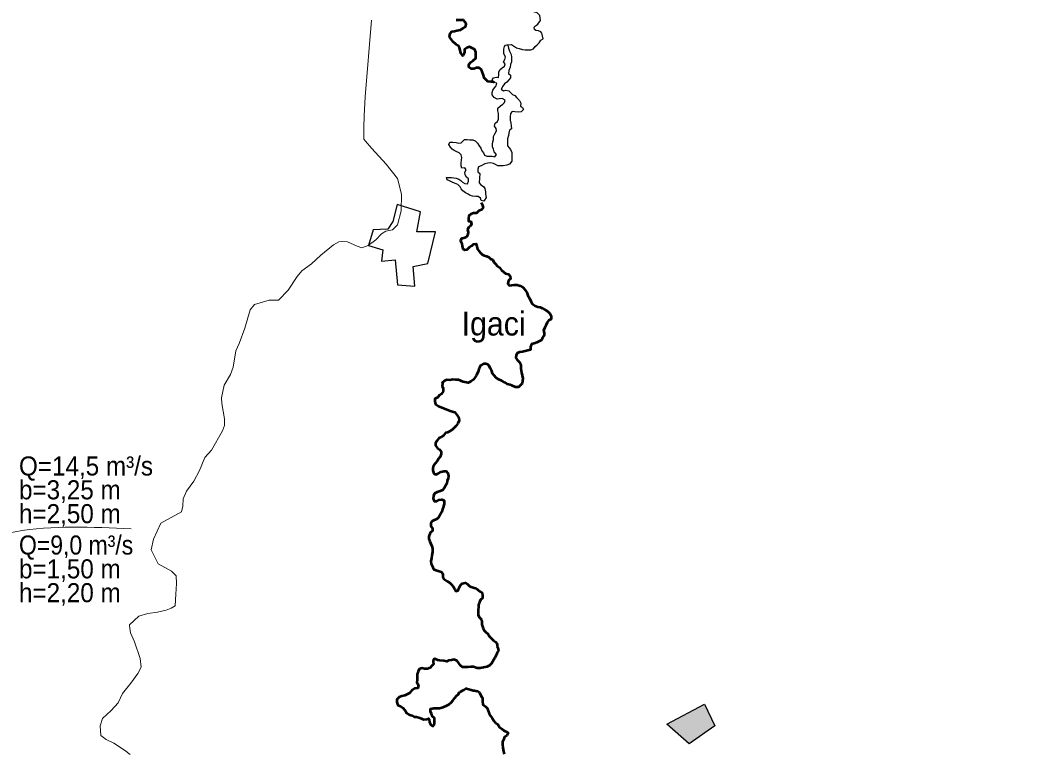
# Model space of a CAD drawing. Extents: x -1643653 to 4543381, y 1624270 to 13878484.
# Drawn here: x 752066 to 773010, y 8933563 to 8948961 of the extents above; entities that cross this region are included whole.
import ezdxf

# ---------------------------------------------------------------- set-up
doc = ezdxf.new("R2010")
doc.units = 0
doc.header["$LTSCALE"] = 160
doc.linetypes.add('MEDIUM_DASHED', pattern=[4.5, 3, -1.5])
for name, color, linetype, lineweight in [('10', 7, 'MEDIUM_DASHED', 60), ('14', 7, 'Continuous', 13), ('21', 7, 'Continuous', 25), ('24', 7, 'Continuous', 25), ('50', 7, 'Continuous', 13), ('60', 7, 'Continuous', 13)]:
    doc.layers.add(name, color=color, linetype=linetype, lineweight=lineweight)
doc.layers.add('41', color=7, linetype='Continuous')

msp = doc.modelspace()

# ---------------------------------------------------------------- hatches: boundary and pattern name
at = {"layer": '21'}
msp.add_hatch(color=256, dxfattribs=at).paths.add_polyline_path([(765624.2, 8934185.8), (766418.4, 8934607.9), (766636, 8934155.3), (766095.9, 8933780)])

# ---------------------------------------------------------------- linework, layer by layer
at = {"layer": '10'}
msp.add_open_spline([(753774.9, 8926261.4), (753812.7, 8926399.9), (753812, 8926558.8), (753709.5, 8926687.3), (753566, 8926867.3), (753376.7, 8926916.9), (753227, 8927050.3), (753014.8, 8927239.4), (752804.9, 8927430.3), (752597.6, 8927630.5), (752376.7, 8927843.7), (752192.2, 8928091.3), (752017.6, 8928334.1), (751956, 8928419.6), (752103.6, 8928574.9), (752029.9, 8928655), (751955.6, 8928735.8), (751801.6, 8928688.1), (751721.4, 8928753.8), (751652.2, 8928810.4), (751601.3, 8928901.2), (751523.9, 8928951.3), (751367.8, 8929052.4), (751185.2, 8929119.1), (751030.2, 8929222.8), (750931.1, 8929289.2), (750854.8, 8929393), (750746.4, 8929445), (750665, 8929484.1), (750582.4, 8929520.3), (750499.6, 8929556.1), (750413.3, 8929593.4), (750326.8, 8929630.1), (750240.4, 8929667.2), (750059.5, 8929745.1), (749875.6, 8929807.6), (749709.7, 8929926.4), (749552.8, 8930038.9), (749714.4, 8930314.8), (749771.5, 8930481.9), (749848.6, 8930707.8), (750077.8, 8930926.7), (750119.5, 8931152.3), (750152, 8931328.4), (750058.1, 8931532.9), (749922, 8931707.8), (749753.2, 8931924.7), (749391.3, 8931773.6), (749243.2, 8931979.4), (749032.7, 8932271.9), (748906.3, 8932592.6), (748823.6, 8932929.9), (748786.3, 8933082.2), (748758.3, 8933247.9), (748811.3, 8933399), (748934, 8933748.4), (749210.7, 8934002.5), (749514.7, 8934226), (749629.1, 8934310.1), (749795.5, 8934228.1), (749909.7, 8934329.8), (749982.5, 8934394.6), (750061.5, 8934468.6), (750045.4, 8934552), (750025.6, 8934654.5), (749991.4, 8934758.2), (749959, 8934860.6), (749901, 8935043.9), (749870.4, 8935232.4), (749773.9, 8935403.7), (749725.3, 8935490), (749619.5, 8935521), (749551.8, 8935588.9), (749459.7, 8935681.1), (749373.5, 8935781.5), (749280.2, 8935872.8), (749090.8, 8936058.2), (748862, 8936191), (748663.2, 8936378.9), (748545.5, 8936490.1), (748390.4, 8936617), (748404, 8936773.9), (748412.2, 8936868.5), (748420.5, 8936963.2), (748428.7, 8937057.8)], degree=3, dxfattribs=at)
at = {"layer": '14'}
for points in [[(756356.5, 8940591.2), (756296.6, 8940917.4), (756291.9, 8941034.6), (756343.8, 8941299.3), (756482.2, 8941523.2), (756533.7, 8941676), (756591, 8942022.3), (756657.8, 8942175), (756781.3, 8942495.7), (756894.8, 8942882.6), (756981.8, 8942989.4), (757287.8, 8943085.7), (757486.4, 8943080.2), (757685.9, 8943293.8), (757875.4, 8943578.7), (757972.7, 8943700.8), (758177, 8943848.1), (758371.2, 8944026.1), (758642, 8944244.6), (758749.2, 8944310.6), (758825.7, 8944315.6), (758932.7, 8944310.3), (759136.1, 8944213.1), (759232.8, 8944182.4), (759365.4, 8944228), (759528.8, 8944349.9), (759646.5, 8944477.1), (759733.3, 8944533), (759876, 8944558.2), (759978.3, 8944665), (760060.9, 8944960.3), (760062.2, 8945306.7), (759981.9, 8945637.9), (759743.6, 8945938.9), (759444.2, 8946265.5), (759307.2, 8946418.6), (759276.8, 8946459.4), (759277.1, 8946556.2), (759272.6, 8946703.9), (759283.7, 8946948.4), (759300.4, 8947350.8), (759434.4, 8948959.2)], [(753980.4, 8934477.6), (754123.7, 8934635.3), (754216.1, 8934833.8), (754390.1, 8935047.4), (754533.5, 8935250.9), (754605.3, 8935388.3), (754585.6, 8935566.6), (754469.7, 8935913.2), (754383.8, 8936101.9), (754363.9, 8936249.7), (754364, 8936275.1), (754558.3, 8936453.1), (754747, 8936508.7), (754950.8, 8936538.9), (755129.3, 8936579.4), (755236.5, 8936625), (755318.1, 8936670.7), (755334.3, 8936915.2), (755350.4, 8937139.3), (755340.8, 8937302.3), (755239.3, 8937399.3), (754959.7, 8937552.6), (754813, 8937843.3), (754864.8, 8938067.3), (755018.9, 8938408.3), (755238.3, 8938525.1), (755452.7, 8938641.9), (755478.6, 8938759), (755489.4, 8938916.9), (755556.2, 8939074.7), (755709.8, 8939283.3), (755832.9, 8939512.3), (755940.9, 8939782.1), (756079, 8939934.6), (756314.8, 8940341.7), (756356, 8940453.7), (756356.5, 8940591.2)], [(754379.5, 8933549.8), (754257.6, 8933646.8), (754033.9, 8933789.8), (753871.2, 8933866.5), (753759.4, 8933948.2), (753744.9, 8934152), (753796.4, 8934304.8), (753980.4, 8934477.6)]]:
    msp.add_lwpolyline(points, dxfattribs=at)
at = {"layer": '21'}
for points in [[(759971.8, 8945092.7), (759884.4, 8944737), (759777.9, 8944573.9), (759473.6, 8944557.9), (759374.4, 8944228.2), (759675.4, 8944141.8), (759642.3, 8943899.6), (759934.4, 8943928.7), (759980.7, 8943402.3), (760347, 8943377.8), (760309.6, 8943788.8), (760615.6, 8943855.9), (760776.1, 8944516.6), (760383.6, 8944516.3), (760460.4, 8944936.4)], [(765624.2, 8934185.8), (766418.4, 8934607.9), (766636, 8934155.3), (766095.9, 8933780)]]:
    msp.add_lwpolyline(points, close=True, dxfattribs=at)
at = {"layer": '24', "lineweight": 53}
for p, q in [((761210.9, 8948956.2), (761361.4, 8948961.1)), ((761361.4, 8948961.1), (761210.9, 8948956.2))]:
    msp.add_line(p, q, dxfattribs=at)
at = {"layer": '24'}
for points in [[(762975.5, 8948950.6), (762963.4, 8949056), (762906, 8949108.6), (762836.6, 8949131.3), (762820.1, 8949147.2), (762725, 8949191.5), (762705.8, 8949206.6), (762661.7, 8949253.3), (762654.7, 8949294.5)], [(763037.7, 8948563.4), (763016, 8948657.7), (763008.9, 8948685.8), (762983.9, 8948709.2), (762933.4, 8948733.1), (762882.7, 8948741.6), (762855.1, 8948762.5), (762848.4, 8948813.6), (762871.8, 8948838.7), (762897.5, 8948853.6), (762923.3, 8948873.5), (762959.9, 8948923.9), (762975.6, 8948949.1), (762975.5, 8948950.6)], [(762274.4, 8948440.9), (762371.2, 8948443.4), (762477.5, 8948379.6), (762533.3, 8948364), (762599.3, 8948343.2), (762655.2, 8948337.7), (762711.2, 8948337.4), (762777.3, 8948337), (762828.3, 8948357), (762869.3, 8948402.6), (762910.2, 8948443.1), (762951.2, 8948483.6), (762987.1, 8948534.3), (763037.7, 8948563.4)], [(762294.6, 8948431.6), (762309.4, 8948370.4), (762329.3, 8948309.2), (762354.4, 8948253), (762369.3, 8948196.8), (762368.9, 8948145.9), (762368.5, 8948079.7), (762352.8, 8948023.8), (762342.2, 8947967.8), (762311.3, 8947901.8), (762310.9, 8947840.7), (762351.3, 8947804.7), (762350.9, 8947748.7), (762315, 8947703.1), (762274, 8947657.5), (762222.9, 8947622.2), (762186.9, 8947571.5), (762156, 8947510.5), (762201.5, 8947474.6), (762252.5, 8947489.6), (762313.4, 8947473.9), (762353.8, 8947432.9), (762394.3, 8947396.9), (762439.9, 8947376.3), (762480.3, 8947330.2), (762535.8, 8947273.8), (762565.9, 8947212.5), (762560.5, 8947156.5), (762600.9, 8947125.7), (762621, 8947079.7), (762569.8, 8947034.2), (762508.7, 8947029.5), (762437.6, 8947035), (762381.7, 8947040.5), (762350.9, 8946999.9), (762340.2, 8946928.7), (762339.7, 8946862.4), (762354.5, 8946796.1), (762364.3, 8946740), (762369, 8946678.9), (762328.1, 8946648.6), (762312.4, 8946587.6), (762307, 8946536.7), (762286.2, 8946470.6), (762285.7, 8946394.2), (762285.2, 8946322.8), (762320.5, 8946281.9), (762350.7, 8946240.9), (762375.7, 8946179.6), (762375.3, 8946123.6), (762380, 8946057.4), (762374.5, 8946001.4), (762328.3, 8945935.4), (762272.2, 8945915.4), (762195.8, 8945900.6), (762134.8, 8945901), (762083.9, 8945901.3), (762038.3, 8945927.1), (761992.7, 8945947.8), (761931.8, 8945963.4), (761875.8, 8945958.7), (761809.6, 8945943.9), (761738.1, 8945903.6), (761682, 8945883.6), (761666.4, 8945832.7), (761666, 8945776.7), (761706.4, 8945740.8), (761694.9, 8945542.2), (761725.1, 8945501.2), (761781.5, 8945468.3), (761814.4, 8945424.2), (761825.4, 8945358.2), (761825.4, 8945314.1), (761836.4, 8945237.1), (761803.4, 8945182), (761788.9, 8945159.5), (761738.1, 8945175.1), (761723.2, 8945226.2), (761672.6, 8945257.1), (761621.7, 8945257.4), (761555.6, 8945262.9), (761504.9, 8945278.5), (761459.3, 8945304.3), (761403.6, 8945335.2), (761347.9, 8945376.3), (761312.6, 8945417.3), (761292.5, 8945463.3), (761247.1, 8945509.4), (761176.1, 8945540.4), (761125.4, 8945561.1), (761069.6, 8945586.9), (761024, 8945607.6), (761009.1, 8945658.6), (761059.9, 8945658.3), (761110.8, 8945658), (761161.6, 8945647.5), (761212.4, 8945642.1), (761263.1, 8945621.4), (761308.7, 8945595.6), (761344.1, 8945559.7), (761389.6, 8945528.9)], [(761389.6, 8945528.9), (761450.6, 8945523.4), (761471.3, 8945579.3), (761466.6, 8945630.2), (761426.1, 8945661.1), (761401.1, 8945712.2), (761391.3, 8945768.3), (761422.1, 8945819), (761391.9, 8945859.9), (761330.8, 8945850.2), (761315.9, 8945901.2), (761316.3, 8945967.4), (761321.8, 8946018.3), (761332.3, 8946074.3), (761317.5, 8946135.5), (761272, 8946171.4), (761221.3, 8946192.1), (761165.5, 8946223.1), (761125, 8946253.9), (761089.7, 8946294.9), (761059.6, 8946351.1), (761080.2, 8946396.8), (761141.3, 8946396.4), (761207.4, 8946390.9), (761263.2, 8946380.3), (761314.1, 8946385.1), (761350, 8946420.5), (761385.8, 8946456), (761441.8, 8946455.6), (761497.7, 8946450.2), (761558.7, 8946449.8), (761609.4, 8946429.1), (761659.9, 8946377.8), (761690.1, 8946321.6), (761725.3, 8946270.4), (761750.4, 8946214.2), (761785.7, 8946173.2), (761805.7, 8946122.2), (761856.4, 8946106.6), (761917.4, 8946101.1), (761968.3, 8946100.8), (762019.1, 8946090.2), (762055, 8946135.8), (762009.7, 8946197.3), (761994.7, 8946248.3), (761974.8, 8946299.4), (761970.1, 8946355.4), (761980.6, 8946406.3), (761996.2, 8946457.1), (761991.5, 8946518.3), (762022.4, 8946574.1), (762053.3, 8946635.1), (762048.6, 8946686), (762013.3, 8946732.1), (762029, 8946793.1), (762075.1, 8946833.6), (762095.7, 8946879.3), (762096.2, 8946945.5), (762096.5, 8946996.4), (762086.8, 8947057.6), (762082.1, 8947113.7), (762138.3, 8947159.2), (762189.4, 8947194.5), (762225.3, 8947229.9), (762235.8, 8947280.8), (762175, 8947311.8), (762119, 8947307), (762068.1, 8947302.3), (762007.3, 8947338.3), (761967, 8947389.5), (761967.3, 8947440.4), (761977.9, 8947491.3), (762013.8, 8947536.9), (762049.7, 8947577.4), (762060.2, 8947633.4), (761999.3, 8947649.1), (761964.1, 8947705.3), (761994.9, 8947745.9), (762045.8, 8947760.8), (762096.7, 8947755.4), (762107.2, 8947816.5), (762107.6, 8947872.5), (762133.4, 8947923.3), (762174.3, 8947958.7), (762220.3, 8947989), (762235.9, 8948039.8), (762205.7, 8948080.7), (762231.5, 8948131.5), (762247.1, 8948187.4), (762212, 8948248.8), (762212.3, 8948299.7), (762212.7, 8948350.7), (762226.4, 8948402.4), (762246.6, 8948432.3), (762274.4, 8948440.9), (762294.6, 8948431.6)]]:
    msp.add_lwpolyline(points, dxfattribs=at)
at = {"layer": '24', "lineweight": 53}
for points in [[(762015.2, 8947645), (761987.8, 8947662.2), (761936.9, 8947662.5), (761870.9, 8947668), (761835.5, 8947709), (761800.2, 8947750), (761780.2, 8947801), (761760.3, 8947857.2), (761740.3, 8947913.3), (761694.9, 8947959.5), (761638.9, 8947954.7), (761577.7, 8947934.7), (761526.9, 8947935), (761476.3, 8947971), (761476.6, 8948027), (761517.6, 8948072.6), (761568.7, 8948107.9), (761625, 8948158.5), (761625.5, 8948219.6), (761620.8, 8948285.9), (761600.9, 8948342), (761489.4, 8948398.8), (761433.3, 8948378.7), (761387.2, 8948338.3), (761386.8, 8948277.2), (761350.7, 8948206.1), (761310.4, 8948262.3), (761295.6, 8948328.7), (761280.7, 8948379.7), (761255.6, 8948425.7), (761204.9, 8948451.5), (761149.3, 8948502.7), (761098.9, 8948564.2), (761068.7, 8948610.2), (761084.4, 8948676.3), (761120.3, 8948716.8), (761176.3, 8948726.7), (761227.3, 8948741.7), (761298.6, 8948756.5), (761359.8, 8948791.8), (761405.8, 8948816.9), (761421.4, 8948872.9), (761391.3, 8948924), (761361.4, 8948961.1)], [(761737.3, 8945134.7), (761755.2, 8945087.5), (761775.2, 8945026.3), (761739.2, 8944980.7), (761683.1, 8944955.6), (761637, 8944910), (761576, 8944905.3), (761514.8, 8944890.4), (761479, 8944855), (761468.4, 8944799), (761468, 8944743), (761518.8, 8944732.5), (761533.7, 8944681.5), (761513.1, 8944635.7), (761467.1, 8944610.6), (761451.5, 8944559.7), (761461.3, 8944508.7), (761455.9, 8944457.8), (761425, 8944407.1), (761374, 8944381.9), (761323.1, 8944377.2), (761302.4, 8944331.5), (761327.5, 8944275.3), (761337.3, 8944219.2), (761347.1, 8944163.1), (761392.7, 8944142.4), (761443.6, 8944147.2), (761489.7, 8944192.7), (761535.7, 8944223), (761576.6, 8944258.4), (761632.6, 8944263.1), (761642.4, 8944212.1), (761657.3, 8944156), (761687.5, 8944115.1), (761717.7, 8944074.1), (761753.1, 8944038.2), (761798.7, 8944017.6), (761849.5, 8944007), (761895.2, 8943986.4), (761930.5, 8943950.5), (761981.2, 8943929.8), (762001.3, 8943883.8), (762036.6, 8943842.8), (762071.9, 8943801.9), (762117.5, 8943771), (762157.7, 8943709.6), (762203.3, 8943678.8), (762243.7, 8943642.8), (762304.7, 8943627.2), (762340, 8943586.2), (762349.8, 8943530.1), (762308.8, 8943494.7), (762293.1, 8943428.6), (762323.4, 8943387.7), (762374.3, 8943397.5), (762425.2, 8943407.4), (762486.2, 8943407), (762552.2, 8943386.2), (762613, 8943350.1), (762653.4, 8943309.1), (762693.7, 8943242.6), (762713.6, 8943181.4), (762748.8, 8943125.1), (762773.8, 8943063.8), (762803.9, 8943007.6)], [(762803.9, 8943007.6), (762864.7, 8942966.5), (762920.5, 8942940.7), (762971.3, 8942935.2), (763016.9, 8942914.6), (763077.7, 8942878.5), (763133.4, 8942842.5), (763173.8, 8942801.5), (763203.9, 8942745.3), (763203.5, 8942684.1), (763147.4, 8942659), (763116.6, 8942613.4), (763095.9, 8942567.7), (763070.1, 8942511.8), (763044.2, 8942445.8), (763054, 8942394.8), (763058.8, 8942343.8), (763022.9, 8942303.3), (763002.2, 8942247.4), (762946, 8942217.2), (762900.1, 8942197.1), (762849.1, 8942177), (762787.9, 8942157.1), (762767.2, 8942101.2), (762766.8, 8942045.1), (762710.7, 8942025.1), (762659.8, 8942010.2), (762598.7, 8942000.3), (762537.6, 8941995.7), (762486.6, 8941970.5), (762465.9, 8941924.8), (762460.5, 8941873.9), (762490.7, 8941832.9), (762526.1, 8941797.1), (762561.4, 8941756.1), (762566.1, 8941705.1), (762565.7, 8941649.1)], [(762565.7, 8941649.1), (762580.6, 8941564.2), (762580.6, 8941564.2), (762611.1, 8941442.4), (762595.8, 8941335.7), (762519.6, 8941259.6), (762453.6, 8941259.6), (762377.4, 8941292.5), (762340.6, 8941308.9), (762279.2, 8941321.2), (762230.1, 8941353.9), (762164.6, 8941394.8), (762103.2, 8941419.3), (762051.3, 8941456.8), (762010.3, 8941499.8), (761975, 8941545.9), (761955, 8941597), (761924.9, 8941658.3), (761899.8, 8941709.4), (761871.3, 8941731.8), (761831, 8941748.4), (761783.1, 8941745.8), (761721.9, 8941715.6), (761696, 8941655.9), (761672.3, 8941589.5), (761634.4, 8941513.7), (761596.5, 8941447.3), (761568.1, 8941409.3), (761520.8, 8941376.1), (761463.9, 8941352.4), (761392.8, 8941366.6), (761355, 8941371.4), (761307.6, 8941390.3), (761257, 8941413), (761201, 8941413.3), (761140, 8941418.8), (761080.2, 8941404.6), (761018.6, 8941409.3), (760966.5, 8941390.3), (760919.1, 8941352.4), (760920.8, 8941343.8), (760920.4, 8941282.7), (760935.3, 8941231.7), (760934.8, 8941165.4), (760904, 8941119.8), (760852.9, 8941089.6), (760830.3, 8941047.1), (760764.8, 8941010.3), (760764.8, 8941010.3), (760764.8, 8940957.1), (760780.4, 8940901.6), (760841.2, 8940860.4), (761104.9, 8940756.8), (761184.4, 8940731.1), (761241.3, 8940660), (761269.7, 8940617.3), (761272.5, 8940557.8), (761245.1, 8940495.9), (761203.9, 8940441), (761135.3, 8940372.3), (761059.8, 8940324.2), (761025.5, 8940310.4), (760989.9, 8940299.1), (760943.7, 8940243.4), (760902.8, 8940208)], [(760902.8, 8940208), (760846.7, 8940188), (760810.8, 8940142.4), (760779.9, 8940086.5), (760779.6, 8940035.6), (760819.8, 8939979.3), (760860.3, 8939948.5), (760895.7, 8939907.5), (760895.3, 8939856.6), (760874.5, 8939795.6), (760833.5, 8939750), (760812.9, 8939704.3), (760777, 8939663.8), (760736, 8939613.1), (760720.3, 8939562.2), (760720, 8939511.3), (760739.9, 8939450.1), (760785.6, 8939429.4), (760831.5, 8939449.5), (760892.7, 8939484.7), (760948.8, 8939499.7), (760999.7, 8939499.3), (761034.9, 8939453.3), (761049.8, 8939397.1), (761044.3, 8939341.1), (761023.6, 8939290.3), (761013.1, 8939239.5), (760977.1, 8939183.7), (760956.5, 8939137.9), (760920.6, 8939097.4), (760874.7, 8939077.3), (760813.5, 8939057.4), (760757.3, 8939027.2), (760736.7, 8938976.4), (760726.1, 8938920.4), (760746.1, 8938869.3), (760802, 8938869)], [(760802, 8938869), (760853.1, 8938894.1), (760909.1, 8938903.9), (760959.8, 8938878.1), (760959.4, 8938817), (760943.7, 8938756), (760923, 8938700.1), (760907.3, 8938644.2), (760881.5, 8938593.4), (760845.5, 8938532.5), (760809.7, 8938497.1), (760707.6, 8938446.8), (760676.7, 8938396), (760676.3, 8938340), (760711.7, 8938304.1), (760711.3, 8938243), (760665.2, 8938202.6), (760639.3, 8938126.3), (760638.9, 8938075.4), (760658.9, 8938024.3), (760678.9, 8937973.2), (760698.9, 8937922.2), (760713.8, 8937871.1), (760713.3, 8937804.9), (760697.6, 8937728.6), (760692.1, 8937672.6), (760676.4, 8937606.5), (760686.2, 8937555.5), (760706.2, 8937509.5), (760736.3, 8937443.1), (760781.9, 8937417.3), (760832.7, 8937406.8), (760898.7, 8937386), (760928.9, 8937345.1), (760933.5, 8937278.8), (760958.6, 8937232.8), (761024.5, 8937191.7), (761075.1, 8937155.7), (761110.4, 8937119.8), (761145.7, 8937073.7), (761181, 8937022.6), (761201, 8936976.6), (761252, 8936996.6), (761272.7, 8937047.4), (761298.5, 8937103.3), (761334.4, 8937138.7), (761400.6, 8937153.6), (761451.3, 8937127.8), (761491.7, 8937086.8), (761547.5, 8937066.1), (761608.4, 8937045.3), (761659, 8937014.4), (761704.5, 8936973.4), (761755.2, 8936947.6), (761765, 8936891.5), (761764.6, 8936835.4), (761723.7, 8936800), (761703, 8936749.2), (761682.2, 8936693.3), (761676.8, 8936642.4), (761671.3, 8936586.4), (761671, 8936535.5), (761670.6, 8936479.5), (761695.7, 8936433.5), (761741.2, 8936387.3)], [(761741.2, 8936387.3), (761751, 8936336.3), (761750.6, 8936280.3), (761775.5, 8936198.6), (761795.5, 8936152.7), (761830.9, 8936116.8), (761876.4, 8936080.8), (761911.7, 8936029.7), (761952.1, 8935988.7), (761992.4, 8935942.6), (762038, 8935916.8), (762073.3, 8935875.8), (762073, 8935819.8), (762081.2, 8935792.2), (762095.5, 8935735.1), (762067, 8935692.3), (762052.7, 8935649.5), (762024.2, 8935578.2), (761953, 8935464), (761910.2, 8935421.2), (761853.2, 8935392.7), (761710.7, 8935364.1), (761653.7, 8935364.1), (761576.7, 8935395.1), (761520.7, 8935390.3), (761459.6, 8935385.6), (761408.8, 8935386), (761342.7, 8935386.4), (761302.2, 8935417.2), (761266.9, 8935468.4), (761231.7, 8935514.4), (761165.7, 8935545.4), (761114.8, 8935530.5), (761048.6, 8935525.8), (761013.4, 8935507.2), (760954.7, 8935515.6), (760870.7, 8935524)], [(760870.7, 8935524), (760828.8, 8935532.4), (760761.6, 8935557.6), (760733.4, 8935543.1), (760728.1, 8935507.2), (760736.5, 8935448.4), (760696.9, 8935410.9), (760666.1, 8935370.4), (760610, 8935350.3), (760543.9, 8935350.8), (760493.1, 8935366.4), (760437.1, 8935346.4), (760411.3, 8935295.6), (760395.6, 8935239.7), (760395.2, 8935173.4), (760389.7, 8935122.5), (760389.3, 8935061.4), (760419.5, 8935010.3), (760403.8, 8934944.2), (760337.6, 8934939.5), (760286.5, 8934909.2), (760235.2, 8934838.3), (760189.3, 8934818.2), (760133.2, 8934793.1), (760072, 8934778.2), (760015.9, 8934758.2), (759969.8, 8934707.5), (759964.3, 8934651.5), (759984.2, 8934585.2), (760045.1, 8934564.4), (760095.7, 8934528.4), (760141.2, 8934477.2), (760166.2, 8934421), (760216.9, 8934395.2), (760277.7, 8934369.4), (760328.4, 8934343.6), (760379.3, 8934343.2), (760425.9, 8934330.8), (760484.7, 8934305.6), (760526.6, 8934288.8), (760593.8, 8934297.2), (760627.3, 8934305.6), (760643.4, 8934290.6), (760648.1, 8934234.5), (760678.2, 8934173.2), (760723.8, 8934147.5), (760754.6, 8934188), (760755, 8934249.1), (760755.5, 8934315.4), (760715, 8934351.3), (760695.1, 8934407.4), (760675, 8934453.4), (760670.3, 8934509.5), (760741.7, 8934524.3), (760797.6, 8934523.9), (760863.7, 8934523.5), (760940.1, 8934543.4), (761011.6, 8934578.6), (761057.5, 8934603.8), (761103.6, 8934644.2), (761149.7, 8934689.8), (761180.6, 8934740.5), (761216.5, 8934786.1), (761257.4, 8934816.4), (761278.1, 8934867.2)], [(761278.1, 8934867.2), (761297.4, 8934864.8), (761368.7, 8934907.6), (761411.4, 8934936.1), (761425.7, 8934936.1), (761525.4, 8934907.6), (761568.2, 8934893.3), (761596.7, 8934893.3), (761653.7, 8934879.1), (761696.5, 8934850.5), (761739.2, 8934764.9), (761760.4, 8934741.9), (761759.9, 8934670.6), (761769.6, 8934599.2), (761825.3, 8934563.2), (761860.6, 8934527.3), (761880.6, 8934466.1), (761900.6, 8934415), (761930.7, 8934363.8), (761966, 8934312.7), (762001.2, 8934261.5), (762036.5, 8934210.4), (762082, 8934179.5), (762122.4, 8934128.3), (762167.9, 8934092.4), (762208.3, 8934056.4), (762254, 8934035.8), (762299.5, 8934004.9), (762273.8, 8933954.1), (762222.7, 8933923.9), (762201.9, 8933862.9), (762181.3, 8933817.2), (762180.9, 8933761.2), (762190.6, 8933689.8), (762200.2, 8933618.4), (762215.1, 8933562.3)]]:
    msp.add_lwpolyline(points, dxfattribs=at)
at = {"layer": '50'}
msp.add_spline([(744731.4, 8934840.9), (748144.5, 8936505), (751968, 8938225.1), (754398.4, 8938284.4)], degree=3, dxfattribs=at)
at = {"layer": '60', "lineweight": 25}
msp.add_spline([(814781, 9009175.5), (814787.2, 9009173.4), (814796.9, 9009173.4), (814799.4, 9009172.4), (814805.1, 9009174.5), (814805.6, 9009176.5), (814811.7, 9009179.5), (814811.7, 9009179.5), (814801.5, 9009181), (814790.7, 9009181.5), (814784.1, 9009183.1), (814777.4, 9009185.1), (814778.4, 9009175.5)], degree=3, dxfattribs=at)

# ---------------------------------------------------------------- texts
at = {"layer": '41', "width": 0.95}
msp.add_text('Igaci', height=500, dxfattribs=at).set_placement((761325, 8942341.6))
at = {"layer": '50'}
for s, width, p in [('Q=14,5 m³/s', 0.95, (752045.4, 8939405.4)), ('b=3,25 m', 0.95, (752045.4, 8938905.4)), ('h=2,50 m', 0.95, (752045.4, 8938405.4)), ('Q=9,0 m³/s', 0.9, (752045.4, 8937747.4)), ('b=1,50 m', 0.95, (752045.4, 8937247.4)), ('h=2,20 m', 0.95, (752045.4, 8936747.4))]:
    msp.add_text(s, height=400, dxfattribs=dict(at, width=width)).set_placement(p)

doc.saveas('drawing.dxf')
